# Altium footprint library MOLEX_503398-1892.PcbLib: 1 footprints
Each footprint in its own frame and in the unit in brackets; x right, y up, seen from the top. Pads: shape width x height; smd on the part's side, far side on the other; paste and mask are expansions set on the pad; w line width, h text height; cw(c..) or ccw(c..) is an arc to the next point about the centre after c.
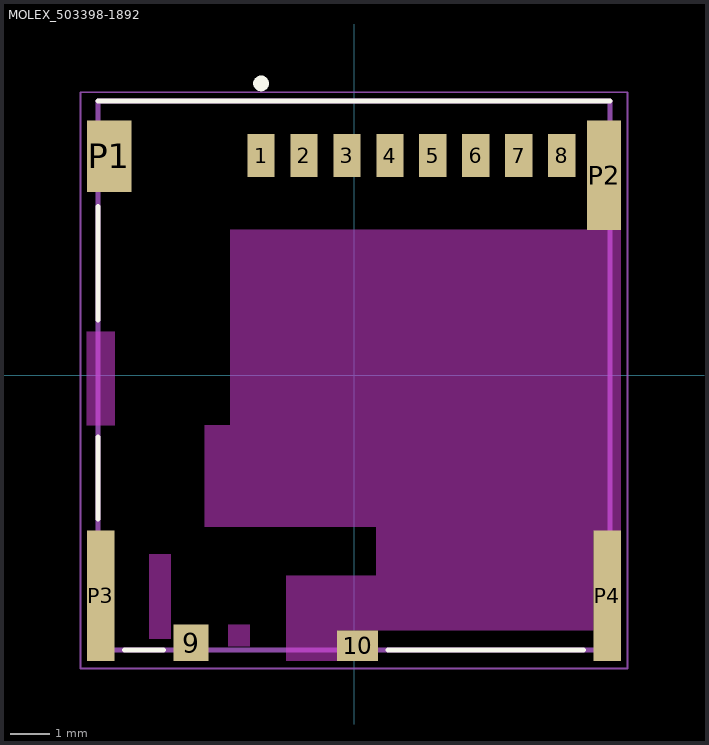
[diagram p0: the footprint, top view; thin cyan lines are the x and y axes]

## MOLEX_503398-1892 [mm]
pads (14):
  rect 0.7x1.1 smd: 1(-2.38,5.625) 2(-1.28,5.625) 3(-0.18,5.625) 4(0.92,5.625) 5(2.02,5.625) 6(3.12,5.625) 7(4.22,5.625) 8(5.32,5.625)
  rect 0.9x0.93 smd: 9(-4.17,-6.84)
  rect 1.05x0.78 smd: 10(0.095,-6.915)
  rect 1.14x1.83 smd: P1(-6.26,5.61)
  rect 0.86x2.8 smd: P2(6.4,5.125)
  rect 0.7x3.33 smd: P3(-6.48,-5.64) P4(6.48,-5.64)
Top Overlay:
  circle w0.2: c-2.38,7.475 r0.1
  lines w0.127: -6.55,-3.675 -6.55,-1.575 ; -6.55,1.425 -6.55,4.325 ; -6.55,7.025 6.55,7.025 ; -5.876,-7.025 -4.874,-7.025 ; 0.874,-7.025 5.876,-7.025
Keep-Out Layer:
  region: 6.83,-3.975 6.13,-3.975 6.13,-6.525 -0.43,-6.525 -0.43,-7.305 -1.73,-7.305 -1.73,-5.125 0.57,-5.125 0.57,-3.875 -3.82,-3.875 -3.82,-1.275 -3.17,-1.275 -3.17,3.725 6.83,3.725
  region: -6.13,-1.276 -6.836,-1.276 -6.836,1.125 -6.13,1.125
  region: -4.685,-6.738 -5.245,-6.738 -5.245,-4.575 -4.685,-4.575
  region: -2.67,-6.93 -3.223,-6.93 -3.223,-6.375 -2.67,-6.375
Mechanical 13:
  circle w0.2: c-2.38,5.775 r0.1
  lines w0.127: -6.55,-7.025 6.55,-7.025 6.55,7.025 -6.55,7.025 -6.55,-7.025
Mechanical 15:
  lines w0.05: -7,-7.5 7,-7.5 7,7.25 -7,7.25 -7,-7.5
3D body "step_temp.STEP": height 1.4, standoff 0, extent -6.55,-7.025 6.55,7.045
